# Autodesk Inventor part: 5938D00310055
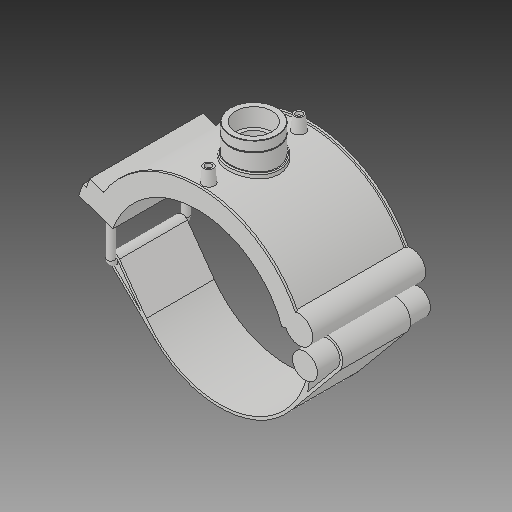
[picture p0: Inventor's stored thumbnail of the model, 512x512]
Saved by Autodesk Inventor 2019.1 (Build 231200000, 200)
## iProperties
Created: 2017-07
Part Number: 5938D00310055
Material: Generic
Description: PLASSON TRANSITION SADDLE 10''DIPS x 2"NPT
Document SubType Name: Modeling
Designer: KIM
Density: 1 g/cm^3
Appearance: Default
Author: KIM
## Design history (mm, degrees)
derived "5938D.ipt"
feature "Solid1::5938D.ipt"
tag "TaggingFeature1"
body "Solid1"
other parameters: "d0" = 280.6, "d1" = 336.72, "d2" = 450.85, "d3" = 70.15, "d4" = 176.022, "d5" = 0, "d40" = 175.0944, "d41" = 79.3184, "d43" = 0, "d45" = 0, "d47" = 215.096, "d48" = 73.6528, "d50" = 0, "d78" = 190.36, "d79" = 15, "d80" = 70.4088, "d82" = 5 deg, "d84" = 4, "d85" = 14, "d86" = 0, "d87" = 3, "d88" = 0, "d96" = 343.4544, "d97" = 3.52044, "d98" = 0, "d102" = 1.69968, "d103" = 56.656, "d104" = 28.0416, "d105" = 0, "d106" = 45.3248, "d108" = 0, "d109" = -15.57867, "d111" = 0.5, "d112" = 0.5, "d113" = 0, "d114" = 0.5, "d117" = 0.56656, "d120" = 140 deg, "d121" = 24.228, "d122" = 20 deg, "d123" = 1346.88, "d124" = 202.032, "d126" = 0, "d143" = 289.018, "d145" = 43.16923, "d149" = 4.209, "d150" = 47.48615, "d153" = 176.022, "d154" = 0, "d156" = 168.36, "d157" = 160 deg, "d159" = 11.224, "d161" = 4.209, "d162" = 105.6132, "d163" = 0, "d164" = 140.3, "d167" = 28.06, "d168" = 164.25366, "d170" = 4.209, "d172" = 0, "d173" = 1, "d175" = 140.3, "d176" = 20 deg, "d177" = 19.642, "d178" = 56.12, "d180" = 0, "d183" = 22.448, "d184" = 15.7136, "d185" = 57.20715, "d186" = 57.20715, "d187" = 168.36, "d188" = 16.836, "d189" = 19.642, "d190" = 0, "d191" = 202.032, "d193" = 11.224, "d194" = 5.7523, "d195" = 90 deg, "d197" = 0, "d199" = 0, "d_" = 280.6, "B_" = 180.34, "H_" = 46.736, "L_" = 176.022, "d_t" = 6, "G_" = 56.656, "d148" = 4.209, "d160" = 4.209, "d169" = 4.209, "d192" = 11.224
